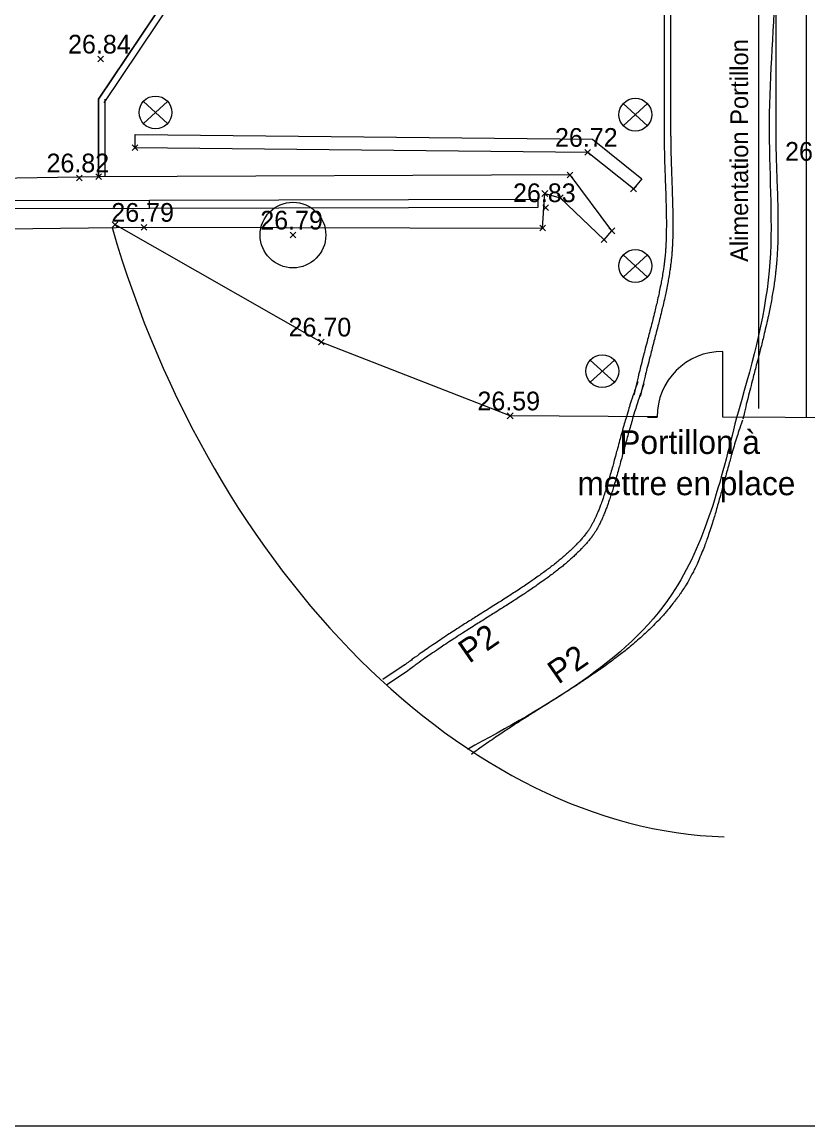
# Model space of a CAD drawing. Extents: x 37864 to 38032, y 453991 to 454052.
# Drawn here: x 37894.08 to 37906.04, y 453990.82 to 454007.62 of the extents above; entities that cross this region are included whole.
import ezdxf

# ---------------------------------------------------------------- set-up
doc = ezdxf.new("R2010")
doc.units = 0
for name, color, linetype in [('DH_CALCUL SURFACE-TEXTE', 7, 'Continuous'), ('GO_POTEAU', 7, 'Continuous'), ('PS_Bolt', 7, 'Continuous'), ('PS_Dim', 7, 'Continuous'), ('PS_Hidden', 7, 'Continuous'), ('PS_Mid', 7, 'Continuous'), ('PS_Object', 7, 'Continuous'), ('PS_Plate', 7, 'Continuous'), ('PS_Solid', 7, 'Continuous'), ('SO_SANITAIRE DETAILLE', 7, 'Continuous')]:
    doc.layers.add(name, color=color, linetype=linetype)

# ---------------------------------------------------------------- blocks, each defined once
blk = doc.blocks.new('DIVERS-P')
blk.add_circle((0, 0), 0.5)
blk = doc.blocks.new('BORNANTI')
for p, q in [((-0.369, -0.338), (0.369, 0.338)), ((-0.369, 0.338), (0.369, -0.338))]:
    blk.add_line(p, q)
blk.add_circle((0, 0), 0.5)
blk = doc.blocks.new('POINT_DISPLAY')
for p, q in [((-0.04375, -0.04375), (0.04375, 0.04375)), ((-0.04375, 0.04375), (0.04375, -0.04375))]:
    blk.add_line(p, q)
blk = doc.blocks.new('POINTCOT')
blk.add_blockref('POINT_DISPLAY', (0, 0))

msp = doc.modelspace()

# ---------------------------------------------------------------- linework, layer by layer
at = {"layer": 'DEFPOINTS'}
msp.add_lwpolyline([(37864.064, 453990.816), (37946.064, 453990.816), (37946.064, 454048.216), (37864.064, 454048.216)], close=True, dxfattribs=at)
at = {"layer": 'PS_Dim'}
for p, q in [((37906.023, 454001.592), (37906.023, 454016.814)), ((37901.929, 454004.915), (37896.018, 454004.902)), ((37901.929, 454004.915), (37901.929, 454004.793)), ((37896.018, 454004.902), (37889.985, 454004.888)), ((37896.018, 454004.78), (37889.985, 454004.766)), ((37896.018, 454004.78), (37896.018, 454004.902)), ((37901.929, 454004.793), (37896.018, 454004.78)), ((37904.746, 454001.606), (37904.746, 454002.606)), ((37903.601, 454001.606), (37903.746, 454001.606))]:
    msp.add_line(p, q, dxfattribs=at)
for points in [[(37903.746, 454001.61), (37901.509, 454001.624), (37898.633, 454002.748), (37895.49, 454004.535)], [(37941.48, 454001.939), (37936.614, 454001.859), (37931.557, 454001.855), (37926.585, 454001.773), (37921.641, 454001.708), (37916.353, 454001.64), (37911.614, 454001.622), (37906.648, 454001.592), (37904.746, 454001.604)]]:
    msp.add_lwpolyline(points, dxfattribs=at)
msp.add_arc((37904.746, 454001.606), 1, 90, 180, dxfattribs=at)
at = {"layer": 'PS_Hidden'}
for p, q in [((37899.896, 453997.827), (37899.571, 453997.61)), ((37899.952, 453997.743), (37899.626, 453997.527))]:
    msp.add_line(p, q, dxfattribs=at)
for points in [[(37902.686, 454016.74), (37904.384, 454013.284), (37905.453, 454010.356), (37905.453, 454005.953), (37905.453, 454003.832), (37904.955, 454001.594)], [(37904.955, 454001.594), (37903.971, 453998.909), (37900.858, 453996.548)]]:
    msp.add_spline(points, degree=3, dxfattribs=at)
for points in [[(37902.776, 454016.784), (37903.066, 454016.194), (37903.501, 454015.308), (37904.008, 454014.275), (37904.262, 454013.759), (37904.389, 454013.501), (37904.446, 454013.385), (37904.466, 454013.344), (37904.471, 454013.335), (37904.473, 454013.33), (37904.48, 454013.316), (37904.493, 454013.289), (37904.507, 454013.261), (37904.589, 454013.096), (37904.666, 454012.948), (37904.821, 454012.649), (37904.899, 454012.498), (37905.049, 454012.194), (37905.122, 454012.04), (37905.256, 454011.728), (37905.318, 454011.57), (37905.423, 454011.25), (37905.466, 454011.087), (37905.529, 454010.758), (37905.549, 454010.59), (37905.553, 454010.399), (37905.553, 454010.378), (37905.553, 454010.356), (37905.553, 454010.356), (37905.553, 454010.355), (37905.553, 454010.354), (37905.553, 454010.352), (37905.553, 454010.347), (37905.553, 454010.338), (37905.553, 454010.32), (37905.553, 454010.264), (37905.553, 454010.13), (37905.553, 454009.843), (37905.553, 454008.938), (37905.553, 454007.787), (37905.553, 454006.636), (37905.553, 454006.138), (37905.553, 454005.966), (37905.553, 454005.958), (37905.553, 454005.953), (37905.553, 454005.95), (37905.553, 454005.938), (37905.553, 454005.907), (37905.554, 454005.876), (37905.554, 454005.815), (37905.555, 454005.774), (37905.557, 454005.652), (37905.559, 454005.57), (37905.567, 454005.323), (37905.574, 454005.158), (37905.584, 454004.827), (37905.588, 454004.661), (37905.587, 454004.328), (37905.582, 454004.162), (37905.566, 454003.955), (37905.562, 454003.913), (37905.556, 454003.851), (37905.554, 454003.83), (37905.549, 454003.789), (37905.547, 454003.768), (37905.534, 454003.665), (37905.522, 454003.583), (37905.481, 454003.337), (37905.448, 454003.174), (37905.374, 454002.85), (37905.334, 454002.689), (37905.251, 454002.369), (37905.209, 454002.209), (37905.128, 454001.89), (37905.088, 454001.731), (37905.053, 454001.572)], [(37901.25, 454016.035), (37901.54, 454015.444), (37901.975, 454014.559), (37902.483, 454013.526), (37902.736, 454013.009), (37902.863, 454012.751), (37902.918, 454012.64), (37902.938, 454012.599), (37902.941, 454012.592), (37902.945, 454012.585), (37902.946, 454012.582), (37902.947, 454012.58), (37902.948, 454012.579), (37902.948, 454012.579), (37902.948, 454012.578), (37902.948, 454012.578), (37902.949, 454012.577), (37902.949, 454012.576), (37902.955, 454012.565), (37902.96, 454012.555), (37902.975, 454012.524), (37902.985, 454012.503), (37903.036, 454012.402), (37903.077, 454012.322), (37903.156, 454012.167), (37903.196, 454012.091), (37903.272, 454011.943), (37903.31, 454011.87), (37903.382, 454011.729), (37903.417, 454011.66), (37903.483, 454011.526), (37903.515, 454011.461), (37903.574, 454011.334), (37903.602, 454011.272), (37903.653, 454011.153), (37903.676, 454011.095), (37903.719, 454010.984), (37903.738, 454010.931), (37903.771, 454010.829), (37903.786, 454010.781), (37903.81, 454010.688), (37903.82, 454010.645), (37903.836, 454010.562), (37903.842, 454010.523), (37903.85, 454010.449), (37903.852, 454010.414), (37903.853, 454010.377), (37903.853, 454010.373), (37903.853, 454010.367), (37903.853, 454010.364), (37903.853, 454010.36), (37903.853, 454010.358), (37903.853, 454010.357), (37903.853, 454010.357), (37903.853, 454010.357), (37903.853, 454010.356), (37903.853, 454010.356), (37903.853, 454010.356), (37903.853, 454010.356), (37903.853, 454010.356), (37903.853, 454010.355), (37903.853, 454010.355), (37903.853, 454010.354), (37903.853, 454010.352), (37903.853, 454010.347), (37903.853, 454010.338), (37903.853, 454010.32), (37903.853, 454010.264), (37903.853, 454010.13), (37903.853, 454009.843), (37903.853, 454008.938), (37903.853, 454007.787), (37903.853, 454006.636), (37903.853, 454006.143), (37903.853, 454005.973), (37903.853, 454005.966), (37903.853, 454005.958), (37903.853, 454005.955), (37903.853, 454005.954), (37903.853, 454005.953), (37903.853, 454005.953), (37903.853, 454005.952), (37903.853, 454005.95), (37903.853, 454005.948), (37903.853, 454005.935), (37903.853, 454005.923), (37903.853, 454005.887), (37903.854, 454005.864), (37903.854, 454005.793), (37903.855, 454005.747), (37903.858, 454005.61), (37903.86, 454005.52), (37903.866, 454005.346), (37903.869, 454005.261), (37903.875, 454005.097), (37903.878, 454005.017), (37903.882, 454004.861), (37903.884, 454004.786), (37903.887, 454004.64), (37903.888, 454004.57), (37903.887, 454004.434), (37903.886, 454004.368), (37903.881, 454004.243), (37903.878, 454004.182), (37903.872, 454004.096), (37903.869, 454004.068), (37903.866, 454004.033), (37903.865, 454004.026), (37903.864, 454004.016), (37903.864, 454004.013), (37903.863, 454004.008), (37903.863, 454004.008), (37903.863, 454004.006), (37903.863, 454004.006), (37903.863, 454004.005), (37903.862, 454004.003), (37903.862, 454004.001), (37903.86, 454003.985), (37903.859, 454003.971), (37903.85, 454003.899), (37903.841, 454003.84), (37903.821, 454003.718), (37903.809, 454003.654), (37903.783, 454003.525), (37903.769, 454003.458), (37903.738, 454003.32), (37903.721, 454003.249), (37903.685, 454003.104), (37903.666, 454003.029), (37903.627, 454002.876), (37903.606, 454002.798), (37903.564, 454002.637), (37903.543, 454002.555), (37903.5, 454002.387), (37903.478, 454002.3), (37903.435, 454002.124), (37903.414, 454002.034), (37903.394, 454001.941)], [(37901.34, 454016.079), (37901.63, 454015.488), (37902.065, 454014.603), (37902.572, 454013.57), (37902.826, 454013.053), (37902.953, 454012.795), (37903.01, 454012.68), (37903.031, 454012.636), (37903.035, 454012.628), (37903.037, 454012.624), (37903.038, 454012.623), (37903.038, 454012.622), (37903.038, 454012.622), (37903.039, 454012.621), (37903.044, 454012.61), (37903.049, 454012.599), (37903.065, 454012.568), (37903.075, 454012.548), (37903.125, 454012.447), (37903.166, 454012.368), (37903.245, 454012.213), (37903.285, 454012.137), (37903.361, 454011.989), (37903.399, 454011.916), (37903.471, 454011.774), (37903.506, 454011.705), (37903.573, 454011.57), (37903.605, 454011.504), (37903.665, 454011.375), (37903.693, 454011.313), (37903.745, 454011.191), (37903.769, 454011.132), (37903.813, 454011.019), (37903.832, 454010.964), (37903.867, 454010.859), (37903.882, 454010.808), (37903.907, 454010.712), (37903.918, 454010.666), (37903.935, 454010.578), (37903.941, 454010.537), (37903.95, 454010.457), (37903.952, 454010.42), (37903.953, 454010.374), (37903.953, 454010.365), (37903.953, 454010.356), (37903.953, 454010.356), (37903.953, 454010.356), (37903.953, 454010.356), (37903.953, 454010.355), (37903.953, 454010.354), (37903.953, 454010.352), (37903.953, 454010.347), (37903.953, 454010.338), (37903.953, 454010.32), (37903.953, 454010.264), (37903.953, 454010.13), (37903.953, 454009.843), (37903.953, 454008.938), (37903.953, 454007.787), (37903.953, 454006.636), (37903.953, 454006.138), (37903.953, 454005.966), (37903.953, 454005.957), (37903.953, 454005.954), (37903.953, 454005.953), (37903.953, 454005.953), (37903.953, 454005.953), (37903.953, 454005.952), (37903.953, 454005.95), (37903.953, 454005.936), (37903.953, 454005.923), (37903.953, 454005.888), (37903.954, 454005.864), (37903.954, 454005.795), (37903.955, 454005.749), (37903.958, 454005.612), (37903.96, 454005.523), (37903.966, 454005.35), (37903.969, 454005.265), (37903.975, 454005.1), (37903.977, 454005.02), (37903.982, 454004.864), (37903.984, 454004.788), (37903.987, 454004.641), (37903.988, 454004.57), (37903.987, 454004.433), (37903.986, 454004.366), (37903.981, 454004.238), (37903.978, 454004.176), (37903.971, 454004.088), (37903.969, 454004.059), (37903.965, 454004.023), (37903.964, 454004.016), (37903.963, 454004.005), (37903.963, 454004.001), (37903.962, 454003.997), (37903.962, 454003.995), (37903.962, 454003.995), (37903.962, 454003.994), (37903.962, 454003.992), (37903.96, 454003.975), (37903.958, 454003.959), (37903.949, 454003.885), (37903.94, 454003.825), (37903.919, 454003.7), (37903.908, 454003.636), (37903.881, 454003.504), (37903.867, 454003.436), (37903.835, 454003.297), (37903.818, 454003.226), (37903.782, 454003.079), (37903.763, 454003.005), (37903.723, 454002.851), (37903.703, 454002.773), (37903.661, 454002.612), (37903.64, 454002.53), (37903.597, 454002.362), (37903.575, 454002.276), (37903.533, 454002.101), (37903.512, 454002.011), (37903.491, 454001.92)], [(37903.453, 454002.144), (37903.421, 454002.058), (37903.392, 454001.973), (37903.338, 454001.807), (37903.313, 454001.726), (37903.265, 454001.566), (37903.243, 454001.488), (37903.2, 454001.335), (37903.18, 454001.261), (37903.14, 454001.117), (37903.121, 454001.046), (37903.085, 454000.911), (37903.067, 454000.845), (37903.031, 454000.718), (37903.014, 454000.658), (37902.979, 454000.542), (37902.962, 454000.486), (37902.928, 454000.381), (37902.911, 454000.332), (37902.877, 454000.239), (37902.86, 454000.196), (37902.827, 454000.117), (37902.81, 454000.08), (37902.787, 454000.031), (37902.779, 454000.015), (37902.763, 453999.986), (37902.756, 453999.972), (37902.741, 453999.946), (37902.733, 453999.933), (37902.719, 453999.91), (37902.712, 453999.899), (37902.699, 453999.879), (37902.692, 453999.87), (37902.686, 453999.861), (37902.685, 453999.861), (37902.685, 453999.861), (37902.685, 453999.86), (37902.685, 453999.86), (37902.685, 453999.86), (37902.685, 453999.86), (37902.685, 453999.86), (37902.685, 453999.86), (37902.684, 453999.86), (37902.684, 453999.859), (37902.682, 453999.856), (37902.68, 453999.854), (37902.676, 453999.848), (37902.673, 453999.845), (37902.666, 453999.835), (37902.66, 453999.828), (37902.633, 453999.793), (37902.61, 453999.765), (37902.559, 453999.708), (37902.532, 453999.679), (37902.473, 453999.619), (37902.442, 453999.589), (37902.375, 453999.527), (37902.34, 453999.496), (37902.265, 453999.432), (37902.226, 453999.4), (37902.144, 453999.335), (37902.1, 453999.302), (37902.011, 453999.235), (37901.964, 453999.201), (37901.867, 453999.133), (37901.817, 453999.098), (37901.714, 453999.028), (37901.661, 453998.993), (37901.551, 453998.922), (37901.495, 453998.885), (37901.381, 453998.812), (37901.322, 453998.775), (37901.203, 453998.7), (37901.142, 453998.662), (37901.018, 453998.584), (37900.956, 453998.544), (37900.828, 453998.464), (37900.764, 453998.423), (37900.634, 453998.339), (37900.568, 453998.296), (37900.435, 453998.208), (37900.368, 453998.163), (37900.233, 453998.071), (37900.165, 453998.023), (37900.028, 453997.925), (37899.96, 453997.875), (37899.891, 453997.823)], [(37903.547, 454002.11), (37903.516, 454002.025), (37903.487, 454001.941), (37903.433, 454001.777), (37903.408, 454001.696), (37903.361, 454001.538), (37903.339, 454001.46), (37903.296, 454001.309), (37903.276, 454001.235), (37903.237, 454001.091), (37903.218, 454001.02), (37903.181, 454000.884), (37903.163, 454000.818), (37903.127, 454000.691), (37903.11, 454000.63), (37903.075, 454000.512), (37903.057, 454000.456), (37903.022, 454000.349), (37903.005, 454000.299), (37902.97, 454000.204), (37902.953, 454000.159), (37902.918, 454000.077), (37902.901, 454000.039), (37902.868, 453999.969), (37902.851, 453999.938), (37902.827, 453999.895), (37902.819, 453999.882), (37902.804, 453999.857), (37902.796, 453999.845), (37902.781, 453999.822), (37902.773, 453999.812), (37902.766, 453999.802), (37902.766, 453999.801), (37902.765, 453999.801), (37902.765, 453999.801), (37902.765, 453999.801), (37902.765, 453999.801), (37902.765, 453999.8), (37902.764, 453999.799), (37902.762, 453999.796), (37902.757, 453999.79), (37902.753, 453999.785), (37902.745, 453999.774), (37902.739, 453999.766), (37902.711, 453999.73), (37902.686, 453999.7), (37902.633, 453999.64), (37902.604, 453999.61), (37902.543, 453999.548), (37902.511, 453999.516), (37902.442, 453999.453), (37902.406, 453999.42), (37902.329, 453999.355), (37902.289, 453999.322), (37902.205, 453999.256), (37902.161, 453999.222), (37902.07, 453999.154), (37902.022, 453999.12), (37901.924, 453999.051), (37901.874, 453999.016), (37901.769, 453998.945), (37901.716, 453998.91), (37901.606, 453998.838), (37901.549, 453998.801), (37901.434, 453998.728), (37901.376, 453998.691), (37901.256, 453998.615), (37901.195, 453998.577), (37901.072, 453998.499), (37901.009, 453998.46), (37900.882, 453998.379), (37900.818, 453998.338), (37900.688, 453998.255), (37900.622, 453998.212), (37900.49, 453998.125), (37900.424, 453998.08), (37900.29, 453997.989), (37900.222, 453997.942), (37900.087, 453997.845), (37900.02, 453997.795), (37899.952, 453997.743)], [(37905.049, 454001.559), (37905.002, 454001.429), (37904.958, 454001.296), (37904.877, 454001.023), (37904.839, 454000.884), (37904.763, 454000.604), (37904.725, 454000.463), (37904.647, 454000.183), (37904.606, 454000.043), (37904.516, 453999.769), (37904.467, 453999.633), (37904.357, 453999.37), (37904.296, 453999.242), (37904.192, 453999.058), (37904.155, 453998.998), (37904.096, 453998.911), (37904.076, 453998.882), (37904.054, 453998.852), (37904.053, 453998.852), (37904.052, 453998.85), (37904.051, 453998.849), (37904.049, 453998.846), (37904.045, 453998.841), (37904.036, 453998.829), (37904.018, 453998.805), (37904.002, 453998.784), (37903.905, 453998.661), (37903.812, 453998.556), (37903.616, 453998.357), (37903.512, 453998.262), (37903.297, 453998.078), (37903.185, 453997.99), (37902.956, 453997.819), (37902.838, 453997.736), (37902.598, 453997.574), (37902.476, 453997.495), (37902.231, 453997.338), (37902.108, 453997.261), (37901.862, 453997.106), (37901.74, 453997.029), (37901.498, 453996.873), (37901.378, 453996.795), (37901.144, 453996.634), (37901.029, 453996.553), (37900.919, 453996.469)]]:
    msp.add_open_spline(points, degree=3, dxfattribs=at)
at = {"layer": 'PS_Mid'}
msp.add_lwpolyline([(37895.934, 454004.494), (37902.003, 454004.482), (37902.037, 454005.008), (37902.272, 454004.945), (37902.939, 454004.305), (37903.058, 454004.44), (37902.422, 454005.291), (37895.242, 454005.264), (37889.943, 454005.178), (37889.991, 454004.425), (37895.934, 454004.494)], dxfattribs=at)
at = {"layer": 'PS_Object'}
msp.add_line((37905.292, 454016.464), (37905.292, 454001.738), dxfattribs=at)
msp.add_lwpolyline([(37889.343, 454030.528), (37899.117, 454030.549), (37899.54, 454012.849), (37895.242, 454006.442), (37895.242, 454005.264), (37889.943, 454005.178)], dxfattribs=at)
at = {"layer": 'PS_Solid'}
msp.add_lwpolyline([(37895.799, 454005.906), (37902.761, 454005.835), (37903.512, 454005.234), (37903.387, 454005.078), (37902.69, 454005.635), (37895.797, 454005.706), (37895.799, 454005.906)], dxfattribs=at)
at = {"layer": 'SO_SANITAIRE DETAILLE'}
for p, q in [((37895.242, 454006.442), (37899.54, 454012.849)), ((37895.325, 454006.386), (37899.623, 454012.793)), ((37895.242, 454005.264), (37895.242, 454006.442)), ((37895.342, 454005.264), (37895.342, 454006.442))]:
    msp.add_line(p, q, dxfattribs=at)
msp.add_ellipse((37903.18, 454006.586), major_axis=(3.419, -11.126), ratio=0.688173, start_param=4.689266, end_param=6.053816, dxfattribs=at)

# ---------------------------------------------------------------- block references
at = {"layer": 'DH_CALCUL SURFACE-TEXTE', "rotation": 2.2526485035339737e-05}
for p in [(37895.275, 454007.055), (37895.797, 454005.706), (37902.69, 454005.635), (37894.947, 454005.246), (37895.242, 454005.264), (37902.422, 454005.291), (37903.387, 454005.078), (37902.037, 454005.008), (37902.272, 454004.945), (37902.051, 454004.794), (37895.49, 454004.535), (37895.934, 454004.494), (37898.202, 454004.376), (37902.003, 454004.482), (37903.058, 454004.44), (37902.939, 454004.305), (37898.633, 454002.748), (37901.509, 454001.624)]:
    msp.add_blockref('POINTCOT', p, dxfattribs=at)
at = {"layer": 'PS_Bolt', "xscale": 0.5000000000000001, "yscale": 0.5, "rotation": 2.2526485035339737e-05}
for p in [(37896.108, 454006.242), (37903.415, 454006.208), (37903.415, 454003.905), (37902.912, 454002.304)]:
    msp.add_blockref('BORNANTI', p, dxfattribs=at)
at = {"layer": 'PS_Plate', "rotation": 2.2526485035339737e-05}
msp.add_blockref('DIVERS-P', (37898.202, 454004.376), dxfattribs=at)

# ---------------------------------------------------------------- texts
at = {"layer": 'GO_POTEAU'}
for s, p in [('26.84', (37894.777, 454007.139)), ('26.72', (37902.192, 454005.719)), ('26.62', (37905.696, 454005.507)), ('26.82', (37894.449, 454005.33)), ('26.83', (37901.553, 454004.877)), ('26.79', (37895.436, 454004.578)), ('26.79', (37897.704, 454004.46)), ('26.70', (37898.135, 454002.832)), ('26.59', (37901.011, 454001.708))]:
    msp.add_text(s, height=0.285, rotation=0, dxfattribs=at).set_placement(p)
at = {"layer": 'PS_Hidden'}
for s, rotation, p in [('Portillon à', 360, (37903.172, 454001.044)), ('mettre en place', 360, (37902.534, 454000.416)), ('P2', 34.5939, (37900.884, 453997.847)), ('P2', 34.5939, (37902.242, 453997.53))]:
    msp.add_text(s, height=0.36, rotation=rotation, dxfattribs=at).set_placement(p)
at = {"layer": 'PS_Object'}
msp.add_text('Alimentation Portillon', height=0.27, rotation=90, dxfattribs=at).set_placement((37905.133, 454003.966))

doc.saveas('drawing.dxf')
